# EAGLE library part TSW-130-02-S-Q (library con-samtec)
THROUGH-HOLE .025" SQ POST HEADER Source: Samtec TSW.pdf
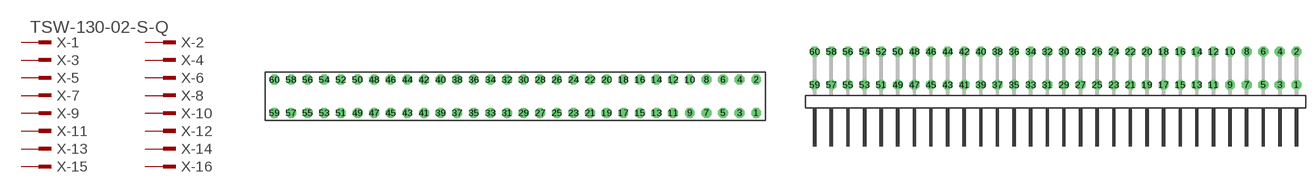
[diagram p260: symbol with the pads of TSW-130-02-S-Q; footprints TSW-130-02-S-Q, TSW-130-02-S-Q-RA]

Designator prefix X; gates -1=MPINV -2=MPIN -3=MPIN -4=MPIN -5=MPIN -6=MPIN -7=MPIN -8=MPIN -9=MPIN -10=MPIN -11=MPIN -12=MPIN -13=MPIN -14=MPIN -15=MPIN -16=MPIN -17=MPIN -18=MPIN -19=MPIN -20=MPIN -21=MPIN -22=MPIN -23=MPIN -24=MPIN -25=MPIN -26=MPIN -27=MPIN -28=MPIN -29=MPIN -30=MPIN -31=MPIN -32=MPIN -33=MPIN -34=MPIN -35=MPIN -36=MPIN -37=MPIN -38=MPIN -39=MPIN -40=MPIN -41=MPIN -42=MPIN -43=MPIN -44=MPIN -45=MPIN -46=MPIN -47=MPIN -48=MPIN -49=MPIN -50=MPIN -51=MPIN -52=MPIN -53=MPIN -54=MPIN -55=MPIN -56=MPIN -57=MPIN -58=MPIN -59=MPIN -60=MPIN

## TSW-130-02-S-Q (OC_FARNELL: unknown; OC_NEWARK: unknown)  [TSW-130-02-S-Q]
1  -1:1  pas
2  -2:1  pas
3  -3:1  pas
4  -4:1  pas
5  -5:1  pas
6  -6:1  pas
7  -7:1  pas
8  -8:1  pas
9  -9:1  pas
10  -10:1  pas
11  -11:1  pas
12  -12:1  pas
13  -13:1  pas
14  -14:1  pas
15  -15:1  pas
16  -16:1  pas
17  -17:1  pas
18  -18:1  pas
19  -19:1  pas
20  -20:1  pas
21  -21:1  pas
22  -22:1  pas
23  -23:1  pas
24  -24:1  pas
25  -25:1  pas
26  -26:1  pas
27  -27:1  pas
28  -28:1  pas
29  -29:1  pas
30  -30:1  pas
31  -31:1  pas
32  -32:1  pas
33  -33:1  pas
34  -34:1  pas
35  -35:1  pas
36  -36:1  pas
37  -37:1  pas
38  -38:1  pas
39  -39:1  pas
40  -40:1  pas
41  -41:1  pas
42  -42:1  pas
43  -43:1  pas
44  -44:1  pas
45  -45:1  pas
46  -46:1  pas
47  -47:1  pas
48  -48:1  pas
49  -49:1  pas
50  -50:1  pas
51  -51:1  pas
52  -52:1  pas
53  -53:1  pas
54  -54:1  pas
55  -55:1  pas
56  -56:1  pas
57  -57:1  pas
58  -58:1  pas
59  -59:1  pas
60  -60:1  pas

## TSW-130-02-S-Q-RA (OC_FARNELL: unknown; OC_NEWARK: unknown)  [TSW-130-02-S-Q-RA]
Pads as for TSW-130-02-S-Q

## Footprint TSW-130-02-S-Q (pad centres in mm)
THROUGH-HOLE .025" SQ POST HEADER Source: Samtec TSW.pdf
drill 1 pad 1.5 octagon: 1 36.83,-2.54; 2 36.83,2.54; 3 34.29,-2.54; 4 34.29,2.54; 5 31.75,-2.54; 6 31.75,2.54; 7 29.21,-2.54; 8 29.21,2.54; 9 26.67,-2.54; 10 26.67,2.54; 11 24.13,-2.54; 12 24.13,2.54; 13 21.59,-2.54; 14 21.59,2.54; 15 19.05,-2.54; 16 19.05,2.54; 17 16.51,-2.54; 18 16.51,2.54; 19 13.97,-2.54; 20 13.97,2.54; 21 11.43,-2.54; 22 11.43,2.54; 23 8.89,-2.54; 24 8.89,2.54; 25 6.35,-2.54; 26 6.35,2.54; 27 3.81,-2.54; 28 3.81,2.54; 29 1.27,-2.54; 30 1.27,2.54; 31 -1.27,-2.54; 32 -1.27,2.54; 33 -3.81,-2.54; 34 -3.81,2.54; 35 -6.35,-2.54; 36 -6.35,2.54; 37 -8.89,-2.54; 38 -8.89,2.54; 39 -11.43,-2.54; 40 -11.43,2.54; 41 -13.97,-2.54; 42 -13.97,2.54; 43 -16.51,-2.54; 44 -16.51,2.54; 45 -19.05,-2.54; 46 -19.05,2.54; 47 -21.59,-2.54; 48 -21.59,2.54; 49 -24.13,-2.54; 50 -24.13,2.54; 51 -26.67,-2.54; 52 -26.67,2.54; 53 -29.21,-2.54; 54 -29.21,2.54; 55 -31.75,-2.54; 56 -31.75,2.54; 57 -34.29,-2.54; 58 -34.29,2.54; 59 -36.83,-2.54; 60 -36.83,2.54

## Footprint TSW-130-02-S-Q-RA (pad centres in mm)
THROUGH-HOLE .025" SQ POST HEADER Source: Samtec TSW.pdf
drill 1 pad 1.5 octagon: 1 36.83,1.524; 2 36.83,6.604; 3 34.29,1.524; 4 34.29,6.604; 5 31.75,1.524; 6 31.75,6.604; 7 29.21,1.524; 8 29.21,6.604; 9 26.67,1.524; 10 26.67,6.604; 11 24.13,1.524; 12 24.13,6.604; 13 21.59,1.524; 14 21.59,6.604; 15 19.05,1.524; 16 19.05,6.604; 17 16.51,1.524; 18 16.51,6.604; 19 13.97,1.524; 20 13.97,6.604; 21 11.43,1.524; 22 11.43,6.604; 23 8.89,1.524; 24 8.89,6.604; 25 6.35,1.524; 26 6.35,6.604; 27 3.81,1.524; 28 3.81,6.604; 29 1.27,1.524; 30 1.27,6.604; 31 -1.27,1.524; 32 -1.27,6.604; 33 -3.81,1.524; 34 -3.81,6.604; 35 -6.35,1.524; 36 -6.35,6.604; 37 -8.89,1.524; 38 -8.89,6.604; 39 -11.43,1.524; 40 -11.43,6.604; 41 -13.97,1.524; 42 -13.97,6.604; 43 -16.51,1.524; 44 -16.51,6.604; 45 -19.05,1.524; 46 -19.05,6.604; 47 -21.59,1.524; 48 -21.59,6.604; 49 -24.13,1.524; 50 -24.13,6.604; 51 -26.67,1.524; 52 -26.67,6.604; 53 -29.21,1.524; 54 -29.21,6.604; 55 -31.75,1.524; 56 -31.75,6.604; 57 -34.29,1.524; 58 -34.29,6.604; 59 -36.83,1.524; 60 -36.83,6.604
